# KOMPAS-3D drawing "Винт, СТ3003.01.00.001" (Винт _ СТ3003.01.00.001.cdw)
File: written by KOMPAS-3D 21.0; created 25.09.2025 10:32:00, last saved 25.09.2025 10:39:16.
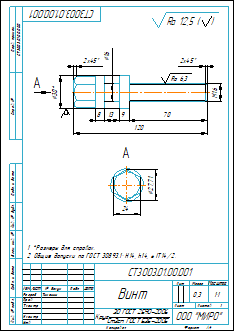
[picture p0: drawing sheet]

Sheet 1: A4, portrait

Document properties: Знак неуказанной шероховатости: 4; Параметр неуказанной шероховатости: Ra 12,5; Масса: 0.303608; L: 120; Полное имя файла: ..\3D\Винт _ СТ3003.01.00.001.m3d

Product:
- Part/product: Винт  | designation СТ3003.01.00.001
    Материал: Круг$d30 ГОСТ 2590-2006;Ст3сп ГОСТ 535-2005$ (density 7850 kg/m3)
    Масса: 0.303608
    additional columns: 120

Title block, sheet 1: Наименование: Винт; designation: СТ3003.01.00.001; Материал: Круг 30 ГОСТ 2590-2006 Ст3сп ГОСТ 535-2005; Масса: 0,3; Количество листов документа: 1; organisation: ООО "МИРО"; Форматы листов документа: A4; stored path: C:\Users\1\Yandex.Disk\Документы\Новая папка\Стапель №2\Стапель _ СТ3003.00.00.000\Опора _ СТ3003.01.00.000\2D\Винт _ СТ3003.01.00.001.cdw; Разработал: Тимонин

Views: Вид 1, Спереди, Вид по стрелке 2, Вид по стрелке А
Referenced files in C:\Users\1\Yandex.Disk\Документы\Новая папка\Стапель №2\Стапель _ СТ3003.00.00.000\Опора _ СТ3003.01.00.000\3D\: Винт _ СТ3003.01.00.001.m3d
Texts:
  Ra 6,3
  Ra 12,5
  Ra 12,5 ( )
  СТ3003.01.00.000
  СТ3003.01.00.001 Винт
Dimensions and other numbers on the sheet: 70; 9; 13; 8; 16; 2; 30; 120; 24; 27,71; 1:1; 1; 0,3

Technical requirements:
  *Размеры для справок.
  Общие допуски по ГОСТ 30893.1: Н14, h14, ± IT14/2.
